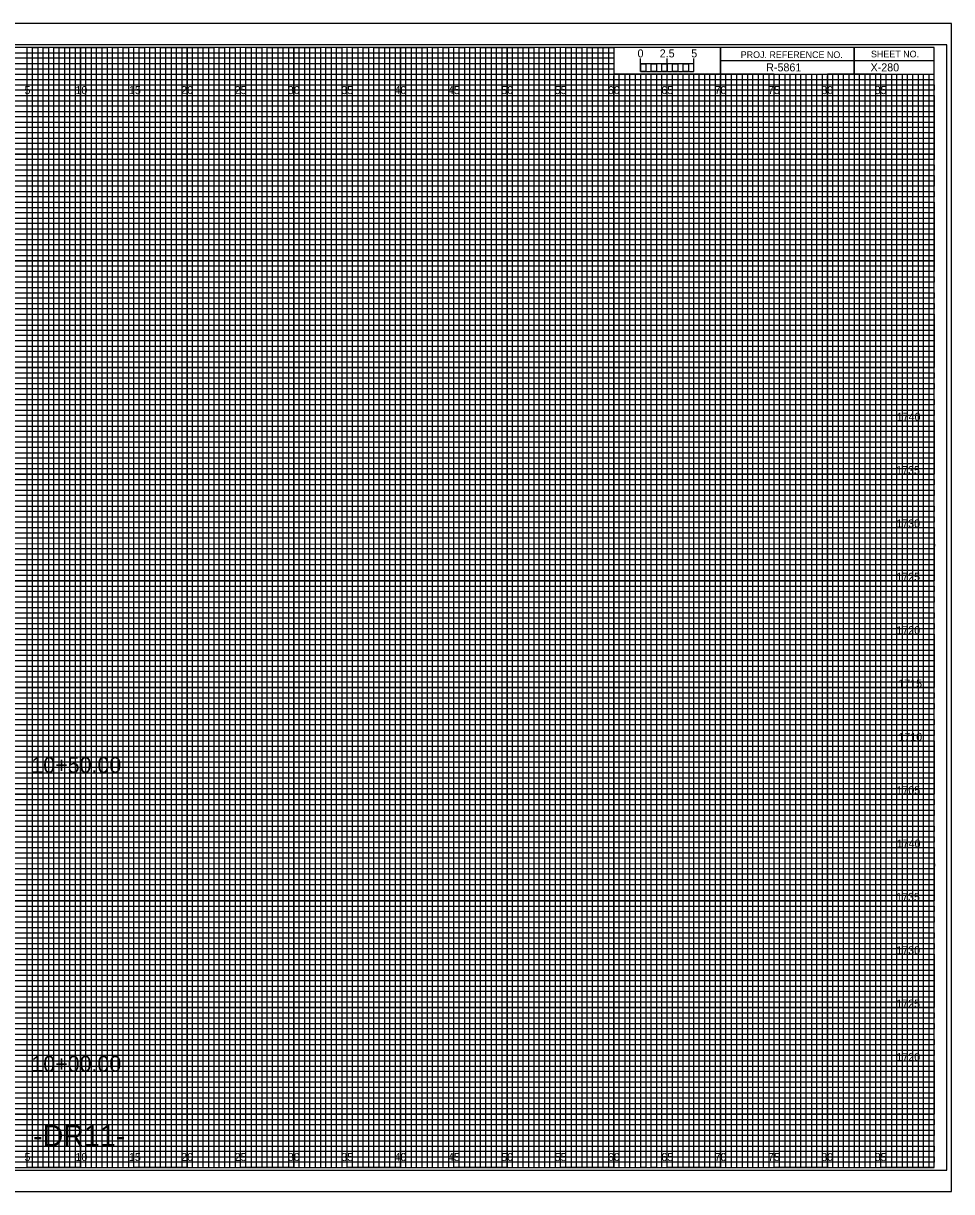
# Model space of a CAD drawing. Extents: x -7 to 162, y -2 to 217.
# Drawn here: x 74.6 to 161.7, y -2.3 to 107.3 of the extents above; entities that cross this region are included whole.
import ezdxf

# ---------------------------------------------------------------- set-up
doc = ezdxf.new("R2010")
doc.units = 0
for name, color, linetype in [('Prop XS Alignment Label', 7, 'Continuous'), ('Prop XS Bar Scale Labels', 7, 'Continuous'), ('Prop XS Elevation Labels', 7, 'Continuous'), ('Prop XS Offset Labels', 7, 'Continuous'), ('Prop XS Project Number', 7, 'Continuous'), ('Prop XS Sheet Number', 7, 'Continuous'), ('Prop XS Station Labels', 7, 'Continuous'), ('Sheet Cross Section CELL', 7, 'Continuous'), ('Sheet Cross Section Grid Major CELL', 7, 'Continuous'), ('Sheet Cross Section Grid Middle CELL', 7, 'Continuous'), ('Sheet Cross Section Grid Minor 1 CELL', 7, 'Continuous'), ('Sheet Cross Section Grid Minor 2 CELL', 7, 'Continuous'), ('Sheet Cross Section Scale CELL', 7, 'Continuous'), ('Sheet Cutting Line CELL', 7, 'Continuous'), ('Sheet DOT Grid CELL', 7, 'Continuous'), ('Sheet Plot Border Inside CELL', 7, 'Continuous'), ('Sheet Plot Border Outside CELL', 7, 'Continuous')]:
    doc.layers.add(name, color=color, linetype=linetype)

msp = doc.modelspace()

# ---------------------------------------------------------------- linework, layer by layer
at = {"layer": 'Sheet Cross Section CELL'}
for p, q in [((152.5, 105), (152.5, 102.5)), ((152.5, 102.5), (152.5, 105)), ((160, 103.75), (140, 103.75)), ((140, 103.75), (140, 102.5)), ((140, 102.5), (160, 102.5))]:
    msp.add_line(p, q, dxfattribs=at)
for points in [[(160, 105), (0, 105), (0, 0), (160, 0)], [(140, 105), (130, 105), (130, 102.52), (140, 102.52)], [(160, 105), (140, 105), (140, 102.5), (160, 102.5)]]:
    msp.add_lwpolyline(points, close=True, dxfattribs=at)
at = {"layer": 'Sheet Cross Section Grid Major CELL'}
for p, q in [((75, 105), (70, 105)), ((75, 0), (75, 105)), ((85, 105), (80, 105)), ((80, 105), (80, 0)), ((85, 0), (85, 105)), ((95, 105), (90, 105)), ((90, 105), (90, 0)), ((95, 0), (95, 105)), ((105, 105), (100, 105)), ((100, 105), (100, 0)), ((105, 0), (105, 105)), ((115, 105), (110, 105)), ((110, 105), (110, 0)), ((115, 0), (115, 105)), ((125, 105), (120, 105)), ((120, 105), (120, 0)), ((125, 0), (125, 105)), ((130, 105), (130, 0)), ((135, 0), (135, 102.5)), ((145, 102.5), (140, 102.5)), ((140, 102.5), (140, 0)), ((145, 0), (145, 102.5)), ((155, 102.5), (150, 102.5)), ((150, 102.5), (150, 0)), ((155, 0), (155, 102.5)), ((80, 0), (75, 0)), ((90, 0), (85, 0)), ((100, 0), (95, 0)), ((110, 0), (105, 0)), ((120, 0), (115, 0)), ((130, 0), (125, 0)), ((140, 0), (135, 0)), ((150, 0), (145, 0)), ((160, 0), (155, 0)), ((160, 0), (160, 0))]:
    msp.add_line(p, q, dxfattribs=at)
for points in [[(0, 100), (160, 100), (160, 95), (0, 95)], [(0, 90), (160, 90), (160, 85), (0, 85)], [(0, 80), (160, 80), (160, 75), (0, 75)], [(0, 70), (160, 70), (160, 65), (0, 65)], [(0, 60), (160, 60), (160, 55), (0, 55)], [(0, 50), (160, 50), (160, 45), (0, 45)], [(0, 40), (160, 40), (160, 35), (0, 35)], [(0, 30), (160, 30), (160, 25), (0, 25)], [(0, 20), (160, 20), (160, 15), (0, 15)], [(0, 10), (160, 10), (160, 5), (0, 5)]]:
    msp.add_lwpolyline(points, dxfattribs=at)
at = {"layer": 'Sheet Cross Section Grid Middle CELL'}
for points in [[(72.5, 0), (77.5, 0), (77.5, 105), (82.5, 105), (82.5, 0), (87.5, 0), (87.5, 105), (92.5, 105), (92.5, 0), (97.5, 0), (97.5, 105), (102.5, 105), (102.5, 0), (107.5, 0), (107.5, 105), (112.5, 105), (112.5, 0), (117.5, 0), (117.5, 105), (122.5, 105), (122.5, 0), (127.5, 0), (127.5, 105), (129.97, 105), (130, 105), (130, 102.5), (132.5, 102.5), (132.5, 0), (137.5, 0), (137.5, 102.5), (142.5, 102.5), (142.5, 0), (147.5, 0), (147.5, 102.5), (152.5, 102.5), (152.5, 0), (157.5, 0), (157.5, 102.5)], [(0, 102.5), (137.5, 102.5)], [(0, 92.5), (160, 92.5), (160, 97.5), (0, 97.5)], [(0, 82.5), (160, 82.5), (160, 87.5), (0, 87.5)], [(0, 72.5), (160, 72.5), (160, 77.5), (0, 77.5)], [(0, 62.5), (160, 62.5), (160, 67.5), (0, 67.5)], [(0, 52.5), (160, 52.5), (160, 57.5), (0, 57.5)], [(0, 42.5), (160, 42.5), (160, 47.5), (0, 47.5)], [(0, 32.5), (160, 32.5), (160, 37.5), (0, 37.5)], [(0, 22.5), (160, 22.5), (160, 27.5), (0, 27.5)], [(0, 12.5), (160, 12.5), (160, 17.5), (0, 17.5)], [(0, 2.5), (160, 2.5), (160, 7.5), (0, 7.5)]]:
    msp.add_lwpolyline(points, dxfattribs=at)
at = {"layer": 'Sheet Cross Section Grid Minor 1 CELL'}
for p, q in [((0, 104.5), (130, 104.5)), ((130, 104.5), (130, 103.99)), ((130, 103.99), (0, 103.99)), ((0, 103.5), (130, 103.5)), ((130, 102.95), (0, 102.95)), ((130, 103.5), (130, 102.95)), ((0, 102), (160, 102))]:
    msp.add_line(p, q, dxfattribs=at)
for points in [[(0, 101.5), (135, 101.5), (160, 101.5), (160, 101), (0, 101)], [(0, 100.5), (160, 100.5), (160, 99.5), (0, 99.5)], [(0, 99), (160, 99), (160, 98.5), (0, 98.49)], [(0, 98), (160, 98), (160, 97), (0, 97)], [(0, 96.5), (160, 96.5), (160, 96), (0, 96)], [(0, 95.5), (160, 95.5), (160, 94.5), (0, 94.5)], [(0, 94), (160, 94), (160, 93.5), (0, 93.5)], [(0, 93), (160, 93), (160, 92), (0, 92)], [(0, 91.5), (160, 91.5), (160, 91), (0, 91)], [(0, 90.5), (160, 90.5), (160, 89.5), (0, 89.5)], [(0, 89), (160, 89), (160, 88.5), (0, 88.5)], [(0, 88), (160, 88), (160, 86.98), (160, 86.5), (160, 86), (0, 86)], [(0, 87), (160, 87), (160, 86.5), (0, 86.5)], [(0, 85.5), (160, 85.5), (160, 84.5), (0, 84.52)], [(0, 84.52), (160, 84.5), (160, 84), (0, 84)], [(0, 83.5), (160, 83.5), (160, 83), (0, 83)], [(0, 82), (160, 82), (160, 81.5), (0, 81.5)], [(0, 81), (160, 81), (160, 80.5), (0, 80.5)], [(-0.04, 79.45), (160, 79.45), (160, 78.94), (-0.04, 78.94)], [(0, 78.5), (160, 78.5), (160, 78), (0, 78)], [(0, 77), (160, 77), (160, 76.5), (0, 76.5)], [(0, 76), (160, 76), (160, 75.5), (0, 75.5)], [(0, 74.5), (160, 74.5), (160, 74), (0, 74)], [(0, 73.5), (160, 73.5), (160, 73), (0, 73)], [(0, 72), (160, 72), (160, 71.5), (0, 71.5)], [(0, 71), (160, 71), (160, 70.5), (0, 70.5)], [(0, 69.5), (160, 69.5), (160, 68.99), (0, 69)], [(0, 68.5), (160, 68.5), (160, 68), (0, 68)], [(0, 67), (160, 67), (160, 66.5), (0, 66.5)], [(0, 66), (160, 66), (160, 65.5), (0, 65.5)], [(0, 64.5), (160, 64.5), (160, 64), (0, 64)], [(0, 63.5), (160, 63.5), (160, 63), (0, 63)], [(0, 62), (160, 62), (160, 61.5), (0, 61.5)], [(0, 61), (160, 61), (160, 60.5), (0, 60.5)], [(0, 59.5), (160, 59.5), (160, 59), (0, 59)], [(0, 58.5), (160.03, 58.45), (160, 58), (0, 58)], [(0, 57), (160, 57), (160, 56.5), (0, 56.5)], [(0, 56), (160, 56), (160, 55.5), (0, 55.5)], [(0, 54.5), (160, 54.5), (160, 54), (0, 54)], [(0, 53.5), (160, 53.5), (160, 53), (0, 53)], [(0, 52), (160, 52), (160, 51.5), (0, 51.5)], [(0, 51), (160, 51), (160, 50.5), (0, 50.5)], [(0, 49.5), (160, 49.5), (160, 49), (0, 49)], [(0, 48.5), (160, 48.5), (160, 48), (0, 48)], [(0, 47), (160, 47), (160, 46.5), (0, 46.5)], [(0, 46), (160, 46), (160, 45.5), (0, 45.5)], [(0, 44.5), (160, 44.5), (160, 44), (0, 44)], [(0, 43.5), (160, 43.5), (160, 43), (0, 43)], [(0, 42), (160, 42), (160, 41.5), (0, 41.5)], [(0, 41), (160, 41), (160, 40.5), (0, 40.5)], [(0, 39.5), (160, 39.5), (160, 38.99), (0, 39)], [(0, 38.5), (160, 38.5), (160, 38), (0, 38)], [(0, 37), (160, 37), (160, 36.5), (0, 36.5)], [(0, 36), (160, 36), (160, 35.5), (0, 35.5)], [(0, 34.5), (160, 34.5), (160, 34), (0, 34)], [(0, 33.5), (160, 33.5), (160, 33), (0, 33)], [(0, 32), (160, 32), (160, 31.5), (0, 31.5)], [(0, 31), (160, 31), (160, 30.5), (0, 30.5)], [(0, 29.5), (160, 29.5), (160, 29), (0, 29)], [(0, 28.5), (160.03, 28.46), (160, 28), (0, 28)], [(0, 27), (160, 27), (160, 26.5), (0, 26.5)], [(0, 26), (160, 26), (160, 25.5), (0, 25.5)], [(0, 24.5), (160, 24.5), (160, 24), (0, 24)], [(0, 23.5), (160, 23.5), (160, 23), (0, 23)], [(0, 22), (160, 22), (160, 21.5), (0, 21.5)], [(0, 21), (160, 21), (160, 20.5), (0, 20.5)], [(0, 19.5), (160, 19.5), (160, 19), (0, 19)], [(0, 18.5), (160, 18.5), (160, 18), (0, 18)], [(0, 17), (160, 17), (160, 16.5), (0, 16.5)], [(0, 16), (160, 16), (160, 15.5), (0, 15.5)], [(0, 14.5), (160, 14.5), (160, 14), (0, 14)], [(0, 13.5), (160, 13.5), (160, 13), (0, 13)], [(0, 12), (160, 12), (160, 11.5), (0, 11.5)], [(0, 11), (160, 11), (160, 10.5), (0, 10.5)], [(0, 9.5), (160, 9.5), (160, 9), (0, 9)], [(0, 8.5), (160, 8.5), (160, 8), (0, 8)], [(0, 7), (160, 7), (160, 6.5), (0, 6.5)], [(0, 6), (160, 6), (160, 5.5), (0, 5.5)], [(0, 4.5), (160, 4.5), (160, 4), (0, 4)], [(0, 3.5), (160, 3.5), (160, 3), (0, 3)], [(0, 2), (160, 2), (160, 1.5), (0, 1.5)], [(0, 1), (160, 1), (160, 0.5), (0, 0.5)]]:
    msp.add_lwpolyline(points, dxfattribs=at)
at = {"layer": 'Sheet Cross Section Grid Minor 2 CELL'}
for p, q in [((133.5, 102.5), (133, 102.5)), ((133, 102.5), (133, 0)), ((133.5, 0), (133.5, 102.5)), ((134.5, 102.5), (134, 102.5)), ((134, 102.5), (134, 0)), ((134.5, 0), (134.5, 102.5)), ((133, 0), (132.5, 0)), ((134, 0), (133.5, 0))]:
    msp.add_line(p, q, dxfattribs=at)
for points in [[(75, 0), (75.5, 0), (75.5, 105), (76, 105), (76, 0)], [(76, 0), (76.5, 0), (76.5, 105), (77, 105), (77, 0)], [(77.5, 0), (78, 0), (78, 105), (78.5, 105), (78.5, 0)], [(78.5, 0), (79, 0), (79, 105), (79.5, 105), (79.5, 0)], [(80, 0), (80.5, 0), (80.5, 105), (81, 105), (81, 0)], [(81, 0), (81.5, 0), (81.5, 105), (82, 105), (82, 0)], [(82.5, 0), (83, 0), (83, 105), (83.5, 105), (83.5, 0)], [(83.5, 0), (84, 0), (84, 105), (84.5, 105), (84.5, 0)], [(85, 0), (85.5, 0), (85.5, 105), (86, 105), (86, 0)], [(86, 0), (86.5, 0), (86.5, 105), (87, 105), (87, 0)], [(87.5, 0), (88, 0), (88, 105), (88.5, 105), (88.5, 0)], [(88.5, 0), (89, 0), (89, 105), (89.5, 105), (89.5, 0)], [(90, 0), (90.5, 0), (90.5, 105), (91, 105), (91, 0)], [(91, 0), (91.5, 0), (91.5, 105), (92, 105), (92, 0)], [(92.5, 0), (93, 0), (93, 105), (93.5, 105), (93.5, 0)], [(93.5, 0), (94, 0), (94, 105), (94.5, 105), (94.5, 0)], [(95, 0), (95.5, 0), (95.5, 105), (96, 105), (96, 0)], [(96, 0), (96.5, 0), (96.5, 105), (97, 105), (97, 0)], [(97.5, 0), (98, 0), (98, 105), (98.5, 105), (98.5, 0)], [(98.5, 0), (99, 0), (99, 105), (99.5, 105), (99.5, 0)], [(100, 0), (100.5, 0), (100.5, 105), (101, 105), (101, 0)], [(101, 0), (101.5, 0), (101.5, 105), (102, 105), (102, 0)], [(102.5, 0), (103, 0), (103, 105), (103.5, 105), (103.5, 0)], [(103.5, 0), (104, 0), (104, 105), (104.5, 105), (104.5, 0)], [(105, 0), (105.5, 0), (105.5, 105), (106, 105), (106, 0)], [(106, 0), (106.5, 0), (106.5, 105), (107, 105), (107, 0)], [(107.5, 0), (108, 0), (108, 105), (108.5, 105), (108.5, 0)], [(108.5, 0), (109, 0), (109, 105), (109.5, 105), (109.5, 0)], [(110, 0), (110.5, 0), (110.5, 105), (111, 105), (111, 0)], [(111, 0), (111.5, 0), (111.5, 105), (112, 105), (112, 0)], [(112.5, 0), (113, 0), (113, 105), (113.5, 105), (113.5, 0)], [(113.5, 0), (114, 0), (114, 105), (114.5, 105), (114.5, 0)], [(115, 0), (115.5, 0), (115.5, 105), (116, 105), (116, 0)], [(116, 0), (116.5, 0), (116.5, 105), (117, 105), (117, 0)], [(117.5, 0), (118, 0), (118, 105), (118.5, 105), (118.5, 0)], [(118.5, 0), (119, 0), (119, 105), (119.5, 105), (119.5, 0)], [(120, 0), (120.5, 0), (120.5, 105), (121, 105), (121, 0)], [(121, 0), (121.5, 0), (121.5, 105), (122, 105), (122, 0)], [(122.5, 0), (123, 0), (123, 105), (123.5, 105), (123.5, 0)], [(123.5, 0), (124, 0), (124, 105), (124.5, 105), (124.5, 0)], [(125, 0), (125.5, 0), (125.5, 105), (126, 105), (126, 0)], [(126, 0), (126.5, 0), (126.5, 105), (127, 105), (127, 0)], [(127.5, 0), (128, 0), (128, 105), (128.5, 105), (128.5, 0)], [(128.5, 0), (129, 0), (129, 105), (129.5, 105), (129.5, 0)], [(130, 0), (130.5, 0), (130.5, 102.5), (131.01, 102.5), (131.01, 0)], [(131, 0), (131.5, 0), (131.5, 102.5), (132, 102.5), (132, 0)], [(135, 0), (135.49, 0), (135.49, 102.5), (136, 102.5), (136, 0)], [(136, 0), (136.5, 0), (136.5, 102.5), (137.03, 102.5), (137.03, 0)], [(137.5, 0), (138, 0), (138, 102.5), (138.5, 102.5), (138.5, 0)], [(138.5, 0), (139, 0), (139, 102.5), (139.5, 102.5), (139.5, 0)], [(140, 0), (140.5, 0), (140.5, 102.5), (141, 102.5), (141, 0)], [(141, 0), (141.5, 0), (141.5, 102.5), (142, 102.5), (142, 0)], [(142.5, 0), (143, 0), (143, 102.5), (143.5, 102.5), (143.5, 0)], [(143.5, 0), (144, 0), (144, 102.5), (144.5, 102.5), (144.5, 0)], [(145, 0), (145.5, 0), (145.5, 102.5), (146, 102.5), (146, 0)], [(146, 0), (146.5, 0), (146.5, 102.5), (147, 102.5), (147, 0)], [(147.5, 0), (148, 0), (148, 102.5), (148.5, 102.5), (148.5, 0)], [(148.5, 0), (149, 0), (149, 102.5), (149.5, 102.5), (149.5, 0)], [(150, 0), (150.5, 0), (150.5, 102.5), (151, 102.5), (151, 0)], [(151, 0), (151.5, 0), (151.5, 102.5), (152, 102.5), (152, 0)], [(152.5, 0), (153, 0), (153, 102.5), (153.5, 102.5), (153.5, 0)], [(153.5, 0), (154, 0), (154, 102.5), (154.5, 102.5), (154.5, 0)], [(155, 0), (155.5, 0), (155.5, 102.5), (156, 102.5), (156, 0)], [(156, 0), (156.5, 0), (156.5, 102.5), (157, 102.5), (157, 0)], [(157.5, 0), (158, 0), (158, 102.5), (158.5, 102.5), (158.5, 0)], [(158.5, 0), (159, 0), (159, 102.5), (159.5, 102.5), (159.5, 0)]]:
    msp.add_lwpolyline(points, dxfattribs=at)
at = {"layer": 'Sheet Cross Section Scale CELL'}
for p, q in [((132.5, 102.75), (132.5, 103.95)), ((132.5, 103.45), (132.5, 103.95)), ((135, 102.75), (135, 103.95)), ((137.5, 102.75), (137.5, 103.95)), ((137.5, 103.45), (137.5, 103.95))]:
    msp.add_line(p, q, dxfattribs=at)
for points in [[(137.5, 103.45), (132.5, 103.45), (132.5, 102.75), (137.5, 102.75)], [(132.5, 103.45), (133, 103.45), (133, 102.75), (132.5, 102.75)], [(133.5, 103.45), (134, 103.45), (134, 102.75), (133.5, 102.75)], [(134.5, 103.45), (135, 103.45), (135, 102.75), (134.5, 102.75)], [(135.5, 103.45), (136, 103.45), (136, 102.75), (135.5, 102.75)], [(136.5, 103.45), (137, 103.45), (137, 102.75), (136.5, 102.75)]]:
    msp.add_lwpolyline(points, close=True, dxfattribs=at)
at = {"layer": 'Sheet Cutting Line CELL'}
for p, q in [((161.65, 107.25), (-6.7, 107.25)), ((-6.7, -2.25), (161.65, -2.25))]:
    msp.add_line(p, q, dxfattribs=at)
at = {"layer": 'Sheet DOT Grid CELL'}
for p, q in [((75, 0), (75, 105)), ((80, 0), (80, 105)), ((85, 0), (85, 105)), ((90, 0), (90, 105)), ((95, 0), (95, 105)), ((100, 0), (100, 105)), ((105, 0), (105, 105)), ((110, 0), (110, 105)), ((115, 0), (115, 105)), ((120, 0), (120, 105)), ((125, 0), (125, 105)), ((130, 0), (130, 102.34)), ((135, 0), (135, 102.34)), ((140, 0), (140, 102.34)), ((145, 0), (145, 102.34)), ((150, 0), (150, 102.34)), ((155, 0), (155, 102.34)), ((0, 100), (160, 100)), ((0, 95), (160, 95)), ((0, 90), (160, 90)), ((0, 85), (160, 85)), ((0, 80), (160, 80)), ((0, 75), (160, 75)), ((0, 70), (160, 70)), ((0, 65), (160, 65)), ((0, 60), (160, 60)), ((0, 55), (160, 55)), ((0, 50), (160, 50)), ((0, 45), (160, 45)), ((0, 40), (160, 40)), ((0, 35), (160, 35)), ((0, 30), (160, 30)), ((0, 25), (160, 25)), ((0, 20), (160, 20)), ((0, 15), (160, 15)), ((0, 10), (160, 10)), ((0, 5), (160, 5))]:
    msp.add_line(p, q, dxfattribs=at)
at = {"layer": 'Sheet Plot Border Inside CELL'}
msp.add_lwpolyline([(-5.4, -0.25), (161.2, -0.25), (161.2, 105.25), (-5.4, 105.25)], close=True, dxfattribs=at)
at = {"layer": 'Sheet Plot Border Outside CELL'}
msp.add_lwpolyline([(-6.7, -2.25), (161.65, -2.25), (161.65, 107.25), (-6.7, 107.25)], close=True, dxfattribs=at)

# ---------------------------------------------------------------- texts
at = {"layer": 'Prop XS Alignment Label'}
msp.add_text('-DR11-', height=2, dxfattribs=at).set_placement((75.56, 2))
at = {"layer": 'Prop XS Bar Scale Labels'}
for s, p in [('2.5', (134.29, 104.06)), ('5', (137.24, 104.06))]:
    msp.add_text(s, height=0.75, dxfattribs=at).set_placement(p)
at = {"layer": 'Prop XS Elevation Labels'}
for s, p in [('1740', (156.5, 70)), ('1735', (156.45, 65)), ('1730', (156.46, 60)), ('1725', (156.46, 55)), ('1720', (156.47, 50)), ('1715', (156.65, 45)), ('1710', (156.66, 40)), ('1705', (156.48, 35)), ('1740', (156.5, 30)), ('1735', (156.45, 25)), ('1730', (156.46, 20)), ('1725', (156.46, 15)), ('1720', (156.47, 10))]:
    msp.add_text(s, height=0.75, dxfattribs=at).set_placement(p)
at = {"layer": 'Prop XS Offset Labels'}
for s, p in [('5', (74.74, 100.62)), ('10', (79.52, 100.62)), ('15', (84.53, 100.62)), ('20', (89.43, 100.62)), ('25', (94.44, 100.62)), ('30', (99.43, 100.62)), ('35', (104.44, 100.62)), ('40', (109.43, 100.62)), ('45', (114.44, 100.62)), ('50', (119.43, 100.62)), ('55', (124.44, 100.62)), ('60', (129.43, 100.62)), ('65', (134.44, 100.62)), ('70', (139.43, 100.62)), ('75', (144.44, 100.62)), ('80', (149.43, 100.62)), ('85', (154.44, 100.62)), ('5', (74.74, 0.62)), ('10', (79.52, 0.62)), ('15', (84.53, 0.62)), ('20', (89.43, 0.62)), ('25', (94.44, 0.62)), ('30', (99.43, 0.62)), ('35', (104.44, 0.62)), ('40', (109.43, 0.62)), ('45', (114.44, 0.62)), ('50', (119.43, 0.62)), ('55', (124.44, 0.62)), ('60', (129.43, 0.62)), ('65', (134.44, 0.62)), ('70', (139.43, 0.62)), ('75', (144.44, 0.62)), ('80', (149.43, 0.62)), ('85', (154.44, 0.62))]:
    msp.add_text(s, height=0.75, dxfattribs=at).set_placement(p)
at = {"layer": 'Prop XS Project Number'}
msp.add_text('R-5861', height=0.75, dxfattribs=at).set_placement((144.27, 102.75))
at = {"layer": 'Prop XS Sheet Number'}
msp.add_text('X-280', height=0.75, dxfattribs=at).set_placement((154.05, 102.75))
at = {"layer": 'Prop XS Station Labels'}
for s, p in [('10+50.00', (75.39, 36.99)), ('10+00.00', (75.39, 8.98))]:
    msp.add_text(s, height=1.5, dxfattribs=at).set_placement(p)
at = {"layer": 'Sheet Cross Section CELL'}
for s, p in [('PROJ. REFERENCE NO.', (141.88, 104)), ('SHEET NO.', (154.09, 104.06))]:
    msp.add_text(s, height=0.625, dxfattribs=at).set_placement(p)
at = {"layer": 'Sheet Cross Section Scale CELL'}
msp.add_text('0', height=0.75, dxfattribs=at).set_placement((132.21, 104.06))

doc.saveas('drawing.dxf')
